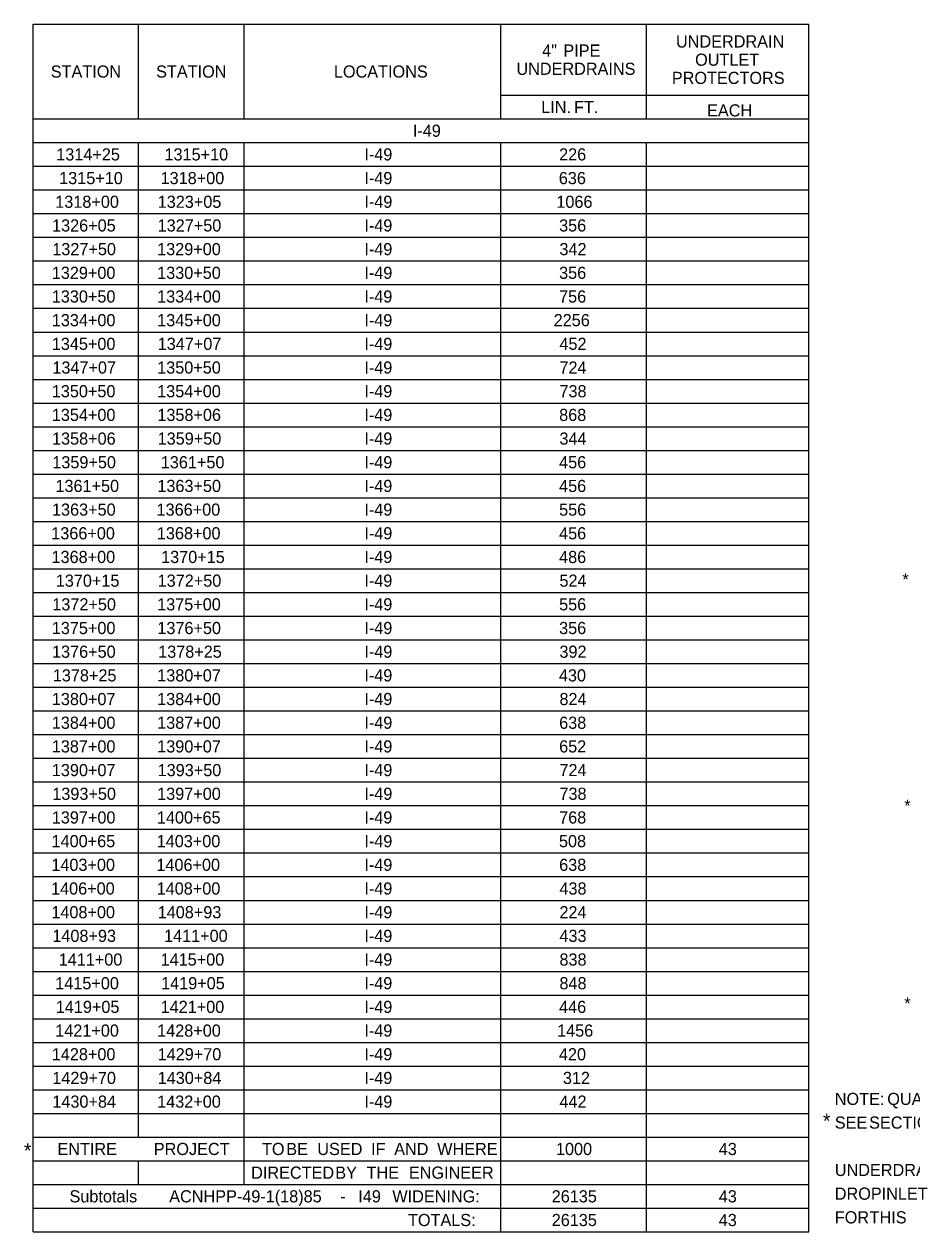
# Model space of a CAD drawing. Extents: x 1226561 to 1228164, y 151309 to 152305.
# Drawn here: x 1226567.8 to 1226933.4, y 151322.3 to 151819.6 of the extents above; entities that cross this region are included whole.
import ezdxf

# ---------------------------------------------------------------- set-up
doc = ezdxf.new("R2010")
doc.units = 0
doc.layers.add('R_Dimension', color=7, linetype='Continuous')

msp = doc.modelspace()

# ---------------------------------------------------------------- linework, layer by layer
at = {"layer": 'R_Dimension'}
for p, q in [((1226571.6, 151819.56), (1226890.97, 151819.56)), ((1226571.6, 151322.31), (1226571.6, 151819.56)), ((1226614.99, 151780.56), (1226614.99, 151819.56)), ((1226658.38, 151780.56), (1226658.38, 151819.56)), ((1226764.22, 151780.56), (1226764.22, 151819.56)), ((1226824.19, 151780.56), (1226824.19, 151819.56)), ((1226890.97, 151322.31), (1226890.97, 151819.56)), ((1226764.22, 151790.31), (1226890.97, 151790.31)), ((1226571.6, 151780.56), (1226890.97, 151780.56)), ((1226571.6, 151770.81), (1226890.97, 151770.81)), ((1226614.99, 151361.31), (1226614.99, 151770.81)), ((1226658.38, 151341.81), (1226658.38, 151770.81)), ((1226764.22, 151322.31), (1226764.22, 151770.81)), ((1226824.19, 151322.31), (1226824.19, 151770.81)), ((1226571.6, 151761.06), (1226890.97, 151761.06)), ((1226571.6, 151751.31), (1226890.97, 151751.31)), ((1226571.6, 151741.56), (1226890.97, 151741.56)), ((1226571.6, 151731.81), (1226890.97, 151731.81)), ((1226571.6, 151722.06), (1226890.97, 151722.06)), ((1226571.6, 151712.31), (1226890.97, 151712.31)), ((1226571.6, 151702.56), (1226890.97, 151702.56)), ((1226571.6, 151692.81), (1226890.97, 151692.81)), ((1226571.6, 151683.06), (1226890.97, 151683.06)), ((1226571.6, 151673.31), (1226890.97, 151673.31)), ((1226571.6, 151663.56), (1226890.97, 151663.56)), ((1226571.6, 151653.81), (1226890.97, 151653.81)), ((1226571.6, 151644.06), (1226890.97, 151644.06)), ((1226571.6, 151634.31), (1226890.97, 151634.31)), ((1226571.6, 151624.56), (1226890.97, 151624.56)), ((1226571.6, 151614.81), (1226890.97, 151614.81)), ((1226571.6, 151605.06), (1226890.97, 151605.06)), ((1226571.6, 151595.31), (1226890.97, 151595.31)), ((1226571.6, 151585.56), (1226890.97, 151585.56)), ((1226571.6, 151575.81), (1226890.97, 151575.81)), ((1226571.6, 151566.06), (1226890.97, 151566.06)), ((1226571.6, 151556.31), (1226890.97, 151556.31)), ((1226571.6, 151546.56), (1226890.97, 151546.56)), ((1226571.6, 151536.81), (1226890.97, 151536.81)), ((1226571.6, 151527.06), (1226890.97, 151527.06)), ((1226571.6, 151517.31), (1226890.97, 151517.31)), ((1226571.6, 151507.56), (1226890.97, 151507.56)), ((1226571.6, 151497.81), (1226890.97, 151497.81)), ((1226571.6, 151488.06), (1226890.97, 151488.06)), ((1226571.6, 151478.31), (1226890.97, 151478.31)), ((1226571.6, 151468.56), (1226890.97, 151468.56)), ((1226571.6, 151458.81), (1226890.97, 151458.81)), ((1226571.6, 151449.06), (1226890.97, 151449.06)), ((1226571.6, 151439.31), (1226890.97, 151439.31)), ((1226571.6, 151429.56), (1226890.97, 151429.56)), ((1226571.6, 151419.81), (1226890.97, 151419.81)), ((1226571.6, 151410.06), (1226890.97, 151410.06)), ((1226571.6, 151400.31), (1226890.97, 151400.31)), ((1226571.6, 151390.56), (1226890.97, 151390.56)), ((1226571.6, 151380.81), (1226890.97, 151380.81)), ((1226571.6, 151371.06), (1226890.97, 151371.06)), ((1226571.6, 151361.31), (1226890.97, 151361.31)), ((1226571.6, 151351.56), (1226890.97, 151351.56)), ((1226614.99, 151341.81), (1226614.99, 151351.56)), ((1226571.6, 151341.81), (1226890.97, 151341.81)), ((1226571.6, 151332.06), (1226890.97, 151332.06)), ((1226571.6, 151322.31), (1226890.97, 151322.31))]:
    msp.add_line(p, q, dxfattribs=at)

# ---------------------------------------------------------------- texts
for s, height, p in [('4"', 5, (1226781.17, 151806.19)), (' PIPE', 5, (1226788.06, 151806.19)), ('UNDERDRAIN', 5, (1226836.3, 151809.94)), ('OUTLET', 5, (1226844.17, 151802.44)), ('STATION', 5, (1226578.79, 151797.56)), ('STATION', 5, (1226622.18, 151797.56)), ('LOCATIONS', 5, (1226695.4, 151797.56)), ('UNDERDRAINS', 5, (1226770.58, 151798.69)), ('PROTECTORS', 5, (1226834.59, 151794.94)), ('LIN.', 5, (1226780.8, 151782.94)), (' FT.', 5, (1226792.45, 151782.94)), ('EACH', 5, (1226849.11, 151781.56)), ('I-49', 5, (1226727.93, 151773.19)), ('1314+25', 5, (1226581.05, 151763.44)), ('1315+10', 5, (1226625.64, 151763.44)), ('I-49', 5, (1226707.94, 151763.44)), ('226', 5, (1226788.16, 151763.44)), ('1315+10', 5, (1226582.25, 151753.69)), ('1318+00', 5, (1226624.03, 151753.69)), ('I-49', 5, (1226707.94, 151753.69)), ('636', 5, (1226788.04, 151753.69)), ('1318+00', 5, (1226580.64, 151743.94)), ('1323+05', 5, (1226622.83, 151743.94)), ('I-49', 5, (1226707.94, 151743.94)), ('1066', 5, (1226787.02, 151743.94)), ('1326+05', 5, (1226579.32, 151734.19)), ('1327+50', 5, (1226622.81, 151734.19)), ('I-49', 5, (1226707.94, 151734.19)), ('356', 5, (1226788.16, 151734.19)), ('1327+50', 5, (1226579.42, 151724.44)), ('1329+00', 5, (1226622.61, 151724.44)), ('I-49', 5, (1226707.94, 151724.44)), ('342', 5, (1226788.3, 151724.44)), ('1329+00', 5, (1226579.22, 151714.69)), ('1330+50', 5, (1226622.61, 151714.69)), ('I-49', 5, (1226707.94, 151714.69)), ('356', 5, (1226788.16, 151714.69)), ('1330+50', 5, (1226579.22, 151704.94)), ('1334+00', 5, (1226622.61, 151704.94)), ('I-49', 5, (1226707.94, 151704.94)), ('756', 5, (1226788.16, 151704.94)), ('1334+00', 5, (1226579.22, 151695.19)), ('1345+00', 5, (1226622.61, 151695.19)), ('I-49', 5, (1226707.94, 151695.19)), ('2256', 5, (1226785.92, 151695.19)), ('1345+00', 5, (1226579.22, 151685.44)), ('1347+07', 5, (1226622.83, 151685.44)), ('I-49', 5, (1226707.94, 151685.44)), ('452', 5, (1226788.3, 151685.44)), ('1347+07', 5, (1226579.44, 151675.69)), ('1350+50', 5, (1226622.61, 151675.69)), ('I-49', 5, (1226707.94, 151675.69)), ('724', 5, (1226788.3, 151675.69)), ('1350+50', 5, (1226579.22, 151665.94)), ('1354+00', 5, (1226622.61, 151665.94)), ('I-49', 5, (1226707.94, 151665.94)), ('738', 5, (1226788.3, 151665.94)), ('1354+00', 5, (1226579.22, 151656.19)), ('1358+06', 5, (1226622.69, 151656.19)), ('I-49', 5, (1226707.94, 151656.19)), ('868', 5, (1226788.18, 151656.19)), ('1358+06', 5, (1226579.3, 151646.44)), ('1359+50', 5, (1226622.81, 151646.44)), ('I-49', 5, (1226707.94, 151646.44)), ('344', 5, (1226788.3, 151646.44)), ('1359+50', 5, (1226579.42, 151636.69)), ('1361+50', 5, (1226624.11, 151636.69)), ('I-49', 5, (1226707.94, 151636.69)), ('456', 5, (1226788.16, 151636.69)), ('1361+50', 5, (1226580.72, 151626.94)), ('1363+50', 5, (1226622.69, 151626.94)), ('I-49', 5, (1226707.94, 151626.94)), ('456', 5, (1226788.16, 151626.94)), ('1363+50', 5, (1226579.3, 151617.19)), ('1366+00', 5, (1226622.37, 151617.19)), ('I-49', 5, (1226707.94, 151617.19)), ('556', 5, (1226788.16, 151617.19)), ('1366+00', 5, (1226578.99, 151607.44)), ('1368+00', 5, (1226622.49, 151607.44)), ('I-49', 5, (1226707.94, 151607.44)), ('456', 5, (1226788.16, 151607.44)), ('1368+00', 5, (1226579.1, 151597.69)), ('1370+15', 5, (1226624.24, 151597.69)), ('I-49', 5, (1226707.94, 151597.69)), ('486', 5, (1226788.16, 151597.69)), ('1370+15', 5, (1226580.86, 151587.94)), ('1372+50', 5, (1226622.81, 151587.94)), ('I-49', 5, (1226707.94, 151587.94)), ('524', 5, (1226788.3, 151587.94)), ('*', 5, (1226929.53, 151588.44)), ('1372+50', 5, (1226579.42, 151578.19)), ('1375+00', 5, (1226622.61, 151578.19)), ('I-49', 5, (1226707.94, 151578.19)), ('556', 5, (1226788.16, 151578.19)), ('1375+00', 5, (1226579.22, 151568.44)), ('1376+50', 5, (1226622.69, 151568.44)), ('I-49', 5, (1226707.94, 151568.44)), ('356', 5, (1226788.16, 151568.44)), ('1376+50', 5, (1226579.3, 151558.69)), ('1378+25', 5, (1226623.02, 151558.69)), ('I-49', 5, (1226707.94, 151558.69)), ('392', 5, (1226788.3, 151558.69)), ('1378+25', 5, (1226579.64, 151548.94)), ('1380+07', 5, (1226622.63, 151548.94)), ('I-49', 5, (1226707.94, 151548.94)), ('430', 5, (1226788.08, 151548.94)), ('1380+07', 5, (1226579.24, 151539.19)), ('1384+00', 5, (1226622.61, 151539.19)), ('I-49', 5, (1226707.94, 151539.19)), ('824', 5, (1226788.3, 151539.19)), ('1384+00', 5, (1226579.22, 151529.44)), ('1387+00', 5, (1226622.61, 151529.44)), ('I-49', 5, (1226707.94, 151529.44)), ('638', 5, (1226788.18, 151529.44)), ('1387+00', 5, (1226579.22, 151519.69)), ('1390+07', 5, (1226622.63, 151519.69)), ('I-49', 5, (1226707.94, 151519.69)), ('652', 5, (1226788.18, 151519.69)), ('1390+07', 5, (1226579.24, 151509.94)), ('1393+50', 5, (1226622.81, 151509.94)), ('I-49', 5, (1226707.94, 151509.94)), ('724', 5, (1226788.3, 151509.94)), ('1393+50', 5, (1226579.42, 151500.19)), ('1397+00', 5, (1226622.61, 151500.19)), ('I-49', 5, (1226707.94, 151500.19)), ('738', 5, (1226788.3, 151500.19)), ('*', 5, (1226930.32, 151495.28)), ('1397+00', 5, (1226579.22, 151490.44)), ('1400+65', 5, (1226622.51, 151490.44)), ('I-49', 5, (1226707.94, 151490.44)), ('768', 5, (1226788.18, 151490.44)), ('1400+65', 5, (1226579.12, 151480.69)), ('1403+00', 5, (1226622.41, 151480.69)), ('I-49', 5, (1226707.94, 151480.69)), ('508', 5, (1226788.1, 151480.69)), ('1403+00', 5, (1226579.03, 151470.94)), ('1406+00', 5, (1226622.29, 151470.94)), ('I-49', 5, (1226707.94, 151470.94)), ('638', 5, (1226788.18, 151470.94)), ('1406+00', 5, (1226578.91, 151461.19)), ('1408+00', 5, (1226622.41, 151461.19)), ('I-49', 5, (1226707.94, 151461.19)), ('438', 5, (1226788.3, 151461.19)), ('1408+00', 5, (1226579.03, 151451.44)), ('1408+93', 5, (1226622.83, 151451.44)), ('I-49', 5, (1226707.94, 151451.44)), ('224', 5, (1226788.3, 151451.44)), ('1408+93', 5, (1226579.44, 151441.69)), ('1411+00', 5, (1226625.44, 151441.69)), ('I-49', 5, (1226707.94, 151441.69)), ('433', 5, (1226788.3, 151441.69)), ('1411+00', 5, (1226582.06, 151431.94)), ('1415+00', 5, (1226624.03, 151431.94)), ('I-49', 5, (1226707.94, 151431.94)), ('838', 5, (1226788.3, 151431.94)), ('1415+00', 5, (1226580.64, 151422.19)), ('1419+05', 5, (1226624.24, 151422.19)), ('I-49', 5, (1226707.94, 151422.19)), ('848', 5, (1226788.3, 151422.19)), ('*', 5, (1226930.32, 151413.87)), ('1419+05', 5, (1226580.86, 151412.44)), ('1421+00', 5, (1226624.03, 151412.44)), ('I-49', 5, (1226707.94, 151412.44)), ('446', 5, (1226788.16, 151412.44)), ('1421+00', 5, (1226580.64, 151402.69)), ('1428+00', 5, (1226622.61, 151402.69)), ('I-49', 5, (1226707.94, 151402.69)), ('1456', 5, (1226787.33, 151402.69)), ('1428+00', 5, (1226579.22, 151392.94)), ('1429+70', 5, (1226622.81, 151392.94)), ('I-49', 5, (1226707.94, 151392.94)), ('420', 5, (1226788.08, 151392.94)), ('1429+70', 5, (1226579.42, 151383.19)), ('1430+84', 5, (1226622.83, 151383.19)), ('I-49', 5, (1226707.94, 151383.19)), ('312', 5, (1226789.72, 151383.19)), ('1430+84', 5, (1226579.44, 151373.44)), ('1432+00', 5, (1226622.61, 151373.44)), ('I-49', 5, (1226707.94, 151373.44)), ('442', 5, (1226788.3, 151373.44)), ('NOTE:', 5, (1226901.7, 151374.55)), (' QUANTITIES', 5, (1226921.46, 151374.55)), ('*', 6, (1226896.82, 151365)), ('SEE', 5, (1226901.7, 151364.8)), (' SECTION', 5, (1226913.98, 151364.8)), ('*', 6, (1226567.7, 151352.76)), ('ENTIRE', 5, (1226581.53, 151353.94)), ('PROJECT', 5, (1226621.23, 151353.94)), ('TO', 5, (1226665.78, 151353.94)), (' BE', 5, (1226673.93, 151353.94)), (' USED', 5, (1226686.72, 151353.94)), (' IF', 5, (1226708.85, 151353.94)), (' AND', 5, (1226718.38, 151353.94)), (' WHERE', 5, (1226736.09, 151353.94)), ('1000', 5, (1226786.86, 151353.94)), ('43', 5, (1226853.92, 151353.94)), ('DIRECTED', 5, (1226661.32, 151344.19)), (' BY', 5, (1226694.12, 151344.19)), (' THE', 5, (1226706.99, 151344.19)), (' ENGINEER', 5, (1226724.43, 151344.19)), ('UNDERDRAINS', 5, (1226901.7, 151345.3)), ('Subtotals', 5, (1226586.51, 151334.44)), (' ACNHPP-49-1(18)85', 5, (1226625.72, 151334.44)), (' I49', 5, (1226703.6, 151334.44)), (' WIDENING:', 5, (1226717.61, 151334.44)), ('26135', 5, (1226785.11, 151334.44)), ('43', 5, (1226853.92, 151334.44)), ('DROP', 5, (1226901.7, 151335.55)), (' INLET', 5, (1226919.14, 151335.55)), (' -', 5, (1226696.16, 151334.44)), ('TOTALS:', 5, (1226725.92, 151324.69)), ('26135', 5, (1226785.11, 151324.69)), ('43', 5, (1226853.92, 151324.69)), ('FOR', 5, (1226901.7, 151325.8)), (' THIS', 5, (1226914.18, 151325.8))]:
    msp.add_text(s, height=height, dxfattribs=at).set_placement(p)

doc.saveas('drawing.dxf')
